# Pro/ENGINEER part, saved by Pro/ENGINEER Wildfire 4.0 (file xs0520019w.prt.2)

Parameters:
  HERSTELLER = "Hersteller"
  PSOL_NOTUSEDSKLST = "SKLST{SKETCH{NAME{"Sketch 37"}MAT{1,0,0,0,0,1,0,0,0,0,1,0,0,0,0,1}SKETCHON{"
  NB = "XS0520019w"
  NN = "XS-Series -Wheel"
  NT = "Thermoplastic Elastomer (x-tra Soft )"
  NBSYN = "$PN.w"
  LINA = "XS0520019w"
  PN = "XS0520019"
  DIA = "5"
  D = "5.000"
  WIDTH = "2"
  W = "2.000"
  HUB = "2-3/16"
  H = "2.188"
  BORE = "1-3/16"
  ID = "1.188"
  ROLL = "052"
  A = "1"
  Z2 = "1"
  KT = "DIA"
